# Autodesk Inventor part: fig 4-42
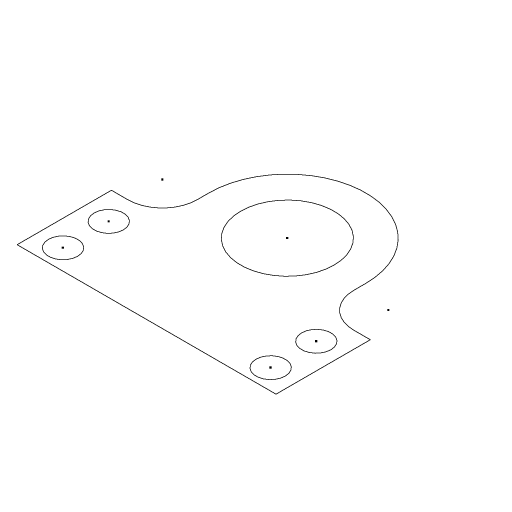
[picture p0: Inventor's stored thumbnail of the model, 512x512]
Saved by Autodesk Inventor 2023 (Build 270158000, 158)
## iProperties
Created: 2004-05
Part Number: fig 4-42
Document SubType Name: Modeling
Designer: CADCIM Technologies
Manufacturer: Standard
Standards Organization: Custom
Density: 1 g/cm^3
Material: Generic
Appearance: Default
Author: CADCIM Technologies
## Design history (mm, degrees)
sketch "Sketch1"
  geometry: L1 (41.331, 50.432)-(41.331, 48.38); L2 (35.331, 42.38)-(32.489, 42.38); L3 (32.489, 42.38)-(32.489, 26.047); L4 (68.481, 50.432)-(68.481, 48.38); L5 (74.481, 42.38)-(77.323, 42.38); L6 (77.323, 42.38)-(77.323, 26.047); L7 (32.489, 26.047)-(77.323, 26.047); C1 r 8.09 at (54.906, 50.432); C2 r 2.534 at (36.931, 29.558); C3 r 2.534 at (36.931, 37.474); C4 r 2.534 at (72.881, 37.474); C5 r 2.534 at (72.881, 29.558); A1 r 13.575 centre (54.906, 50.432) between (68.481, 50.432) and (41.331, 50.432); A2 r 6 centre (35.331, 48.38) between (35.331, 42.38) and (41.331, 48.38); A3 r 6 centre (74.481, 48.38) between (68.481, 48.38) and (74.481, 42.38)
  constraints: 14 end point, 8 centre point, 6 point on circle, 6 tangent, 3 equal length, 2 horizontal, 2 perpendicular, 1 coincident, 1 equal radius, 1 parallel, 1 vertical
